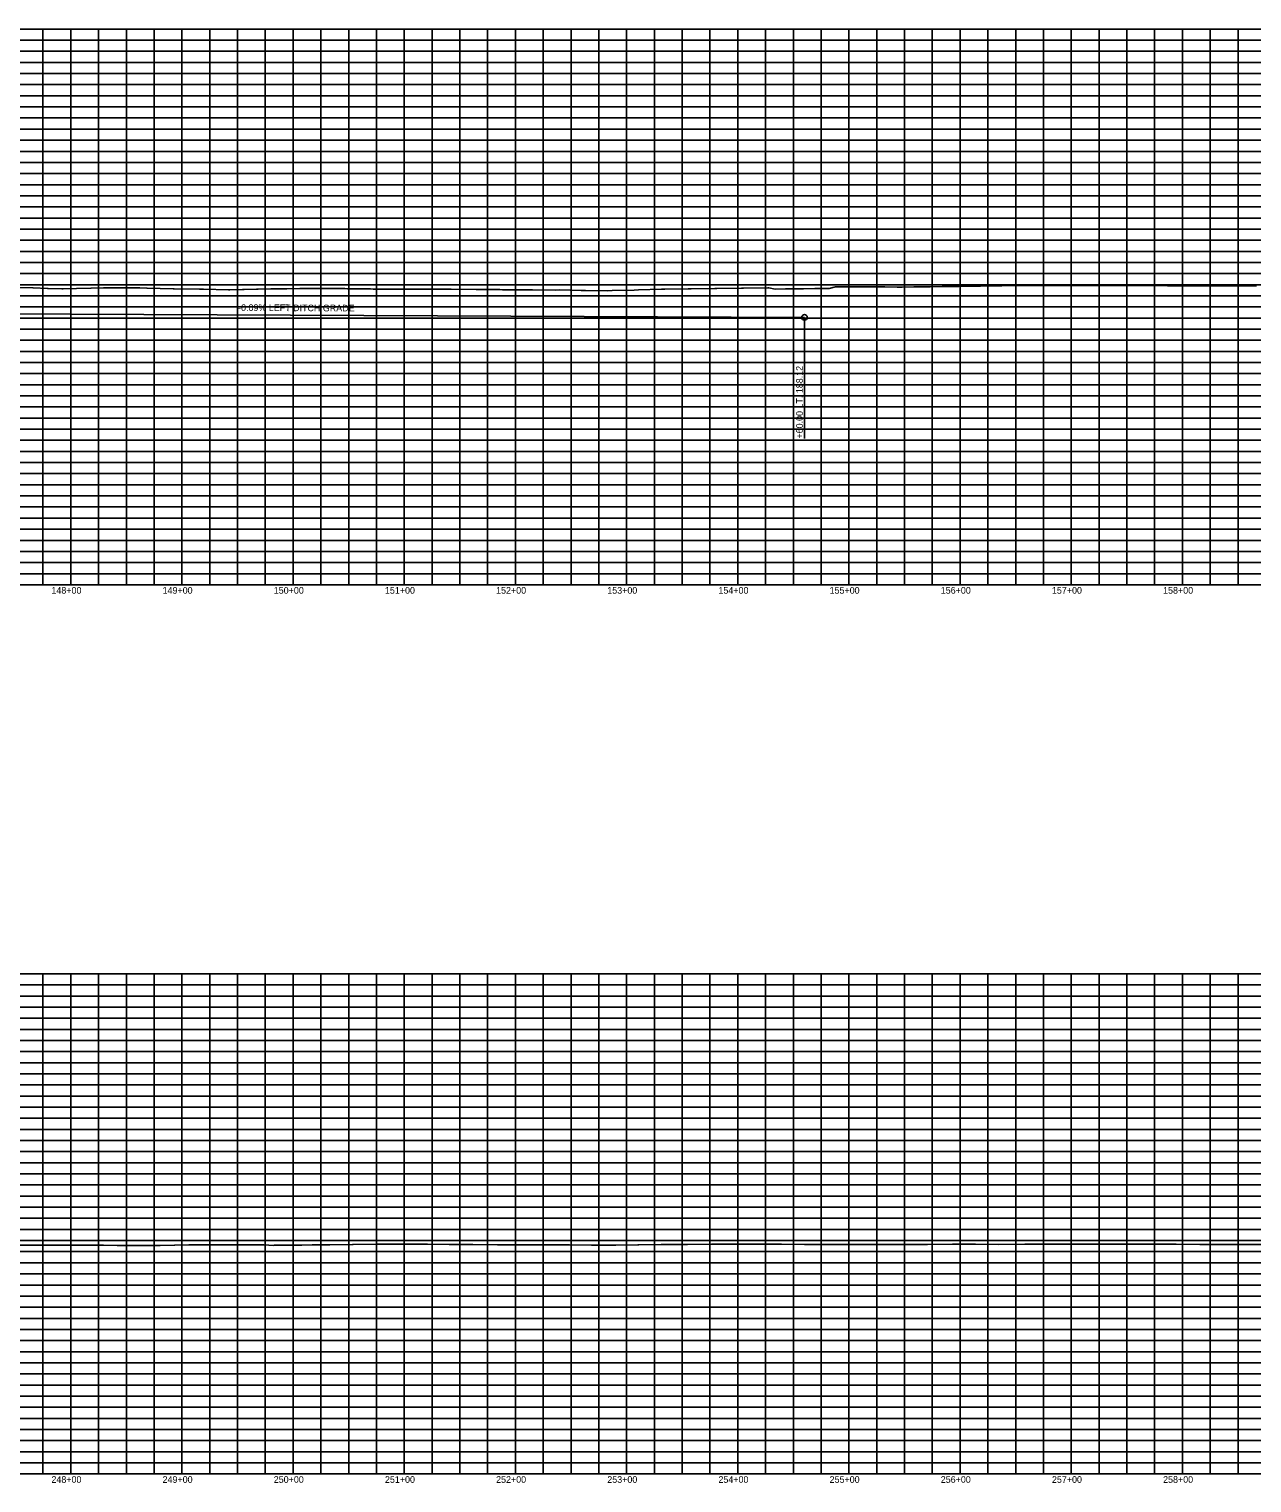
# Model space of a CAD drawing. Extents: x 1399671 to 1408349, y 1930471 to 1933387.
# Drawn here: x 1405087 to 1406187, y 1932071 to 1933379 of the extents above; entities that cross this region are included whole.
import ezdxf

# ---------------------------------------------------------------- set-up
doc = ezdxf.new("R2010")
doc.units = 0
for name, color, linetype in [('R_Exist Surface', 7, 'Continuous'), ('R_Grid', 7, 'Continuous'), ('R_Grid Annot', 7, 'Continuous'), ('R_Vert Alg', 7, 'Continuous'), ('R_Vert Alg Annot', 7, 'Continuous')]:
    doc.layers.add(name, color=color, linetype=linetype)

msp = doc.modelspace()

# ---------------------------------------------------------------- linework, layer by layer
at = {"layer": 'R_Exist Surface'}
for points in [[(1405077.4, 1933146), (1405090.1, 1933145.8), (1405090.3, 1933145.8), (1405090.3, 1933145.8), (1405103.3, 1933145.3), (1405103.8, 1933145.3), (1405116.3, 1933144.9), (1405117.2, 1933144.9), (1405129.4, 1933145.2), (1405142.3, 1933145.5), (1405142.5, 1933145.5), (1405153.5, 1933145.7), (1405155.7, 1933145.7), (1405155.8, 1933145.7), (1405168.7, 1933145.8), (1405170.1, 1933145.8), (1405186.2, 1933145.7), (1405192.7, 1933145.5), (1405193, 1933145.5), (1405216.2, 1933145), (1405217.3, 1933145), (1405240, 1933144.7), (1405241.7, 1933144.6), (1405243.6, 1933144.5), (1405266, 1933144.1), (1405267.4, 1933144.1), (1405278.7, 1933144.3), (1405280.1, 1933144.4), (1405291.4, 1933144.6), (1405292.8, 1933144.6), (1405304.1, 1933144.8), (1405305.5, 1933144.8), (1405316.8, 1933145), (1405318.4, 1933145), (1405330.3, 1933145.1), (1405331.8, 1933145.1), (1405343.8, 1933145.1), (1405345.2, 1933145.1), (1405357.3, 1933145.1), (1405369.6, 1933145.1), (1405370.8, 1933145.1), (1405373, 1933145), (1405393.8, 1933144.8), (1405396.1, 1933144.7), (1405416.9, 1933144.6), (1405419.2, 1933144.6), (1405440.9, 1933144.6), (1405442.8, 1933144.6), (1405465, 1933144.7), (1405466.5, 1933144.6), (1405488.8, 1933144.4), (1405510.2, 1933144.2), (1405512.7, 1933144), (1405533.1, 1933143.9), (1405536.4, 1933143.9), (1405539.4, 1933144), (1405560.1, 1933143.8), (1405563.5, 1933143.9), (1405583.4, 1933143.5), (1405587.2, 1933143.5), (1405606.7, 1933143.1), (1405611.1, 1933143.3), (1405631.1, 1933143.8), (1405634.8, 1933143.9), (1405655.5, 1933144.5), (1405658.6, 1933144.6), (1405679.6, 1933144.8), (1405682.2, 1933145), (1405703.7, 1933145.2), (1405705.4, 1933145.2), (1405727.4, 1933145.5), (1405729.2, 1933145.5), (1405751.2, 1933145.8), (1405752, 1933145.9), (1405757.7, 1933144.7), (1405767, 1933144.8), (1405776.3, 1933144.8), (1405780.4, 1933144.9), (1405783.4, 1933145), (1405793.4, 1933145.1), (1405796.3, 1933145.2), (1405806.4, 1933145.2), (1405812.2, 1933146.8), (1405815, 1933146.8), (1405826, 1933146.7), (1405828.8, 1933146.8), (1405839.9, 1933146.7), (1405842.6, 1933146.7), (1405853.7, 1933146.6), (1405856.4, 1933146.6), (1405867.6, 1933146.5), (1405872.2, 1933146.5), (1405882.6, 1933146.7), (1405893.4, 1933146.8), (1405897.4, 1933146.8), (1405908.2, 1933147), (1405919.3, 1933147.1), (1405923, 1933147.1), (1405938.8, 1933147.3), (1405942.4, 1933147.4), (1405958.2, 1933147.6), (1405961.7, 1933147.6), (1405977.6, 1933147.8), (1405993.5, 1933148), (1405996.9, 1933148), (1406014, 1933148), (1406020, 1933147.9), (1406035.3, 1933147.9), (1406043.2, 1933147.8), (1406053.3, 1933147.8), (1406060.5, 1933147.8), (1406070.7, 1933147.8), (1406081.3, 1933147.8), (1406087.9, 1933147.8), (1406098.5, 1933147.8), (1406105.2, 1933147.8), (1406110.7, 1933147.7), (1406123.1, 1933147.7), (1406130.1, 1933147.7), (1406147.6, 1933147.7), (1406155.4, 1933147.7), (1406164.6, 1933147.7), (1406173.5, 1933147.7), (1406182, 1933147.7), (1406190.8, 1933147.7)], [(1405076.8, 1932284.5), (1405089.3, 1932284.5), (1405089.6, 1932284.5), (1405102.2, 1932284.5), (1405102.4, 1932284.5), (1405115, 1932284.4), (1405115.3, 1932284.4), (1405127.8, 1932284.4), (1405128.1, 1932284.4), (1405140.7, 1932284.3), (1405141, 1932284.3), (1405153.3, 1932284.3), (1405153.6, 1932284.3), (1405166, 1932284.2), (1405166.2, 1932284.2), (1405178.6, 1932284.1), (1405178.9, 1932284.1), (1405191.3, 1932284.1), (1405191.5, 1932284.1), (1405204.4, 1932284.2), (1405204.6, 1932284.2), (1405217.4, 1932284.4), (1405217.7, 1932284.4), (1405230.5, 1932284.6), (1405230.7, 1932284.6), (1405230.9, 1932284.6), (1405243.8, 1932284.7), (1405244, 1932284.7), (1405257.2, 1932284.7), (1405257.5, 1932284.7), (1405270.7, 1932284.7), (1405283.7, 1932284.6), (1405284.1, 1932284.6), (1405297.1, 1932284.6), (1405297.5, 1932284.6), (1405297.8, 1932284.6), (1405306.8, 1932284.2), (1405307.3, 1932284.3), (1405331, 1932284.5), (1405331.5, 1932284.5), (1405332, 1932284.5), (1405341.4, 1932284.6), (1405355.6, 1932284.7), (1405356.2, 1932284.7), (1405357.1, 1932284.7), (1405377.5, 1932284.9), (1405378.3, 1932285), (1405398.8, 1932285.2), (1405399.6, 1932285.2), (1405421.5, 1932285.2), (1405422.3, 1932285.2), (1405444.1, 1932285.2), (1405445, 1932285.2), (1405464.6, 1932285.1), (1405465.4, 1932285.1), (1405485, 1932284.9), (1405486, 1932284.9), (1405508.2, 1932284.8), (1405509.3, 1932284.8), (1405531.4, 1932284.6), (1405532.4, 1932284.6), (1405552.1, 1932284.6), (1405553.1, 1932284.6), (1405572.8, 1932284.6), (1405592.7, 1932284.5), (1405593.7, 1932284.5), (1405613.6, 1932284.4), (1405614.6, 1932284.4), (1405634.4, 1932284.6), (1405635.3, 1932284.6), (1405655.3, 1932284.9), (1405656, 1932284.9), (1405656.7, 1932284.9), (1405678.3, 1932285.1), (1405678.9, 1932285.1), (1405700.5, 1932285.3), (1405701.1, 1932285.3), (1405721.4, 1932285.2), (1405722, 1932285.2), (1405742.2, 1932285.2), (1405743, 1932285.2), (1405763.2, 1932285.2), (1405763.6, 1932285.2), (1405784.2, 1932285.1), (1405784.3, 1932285.1), (1405806.6, 1932285.1), (1405828.5, 1932285), (1405829, 1932285), (1405849.6, 1932285), (1405850, 1932285), (1405850.5, 1932285), (1405871.1, 1932285), (1405871.7, 1932285), (1405894.3, 1932285.1), (1405894.8, 1932285.1), (1405917.4, 1932285.2), (1405918, 1932285.2), (1405937.9, 1932285.2), (1405958.3, 1932285.1), (1405958.4, 1932285.1), (1405982.4, 1932285.2), (1405982.5, 1932285.2), (1406000.2, 1932285.2), (1406006.5, 1932285.2), (1406006.5, 1932285.2), (1406029, 1932285.3), (1406029.2, 1932285.3), (1406051.5, 1932285.4), (1406051.9, 1932285.4), (1406052.3, 1932285.4), (1406072.9, 1932285.4), (1406073.3, 1932285.4), (1406094, 1932285.4), (1406094.4, 1932285.4), (1406096.5, 1932285.4), (1406116.9, 1932285.2), (1406117.3, 1932285.2), (1406118.4, 1932285.2), (1406139.8, 1932285.1), (1406140.2, 1932285.1), (1406145.5, 1932285.1), (1406161.4, 1932285), (1406161.6, 1932285), (1406161.8, 1932285), (1406162.1, 1932285), (1406183.4, 1932285), (1406184, 1932285), (1406204.8, 1932285)]]:
    msp.add_lwpolyline(points, dxfattribs=at)
at = {"layer": 'R_Grid'}
for p, q in [((1400324.2, 1933378.6), (1408224.2, 1933378.6)), ((1400324.2, 1933378.6), (1408224.2, 1933378.6)), ((1405099.2, 1932878.6), (1405099.2, 1933378.6)), ((1405124.2, 1932878.6), (1405124.2, 1933378.6)), ((1405149.2, 1932878.6), (1405149.2, 1933378.6)), ((1405174.2, 1932878.6), (1405174.2, 1933378.6)), ((1405199.2, 1932878.6), (1405199.2, 1933378.6)), ((1405224.2, 1932878.6), (1405224.2, 1933378.6)), ((1405249.2, 1932878.6), (1405249.2, 1933378.6)), ((1405274.2, 1932878.6), (1405274.2, 1933378.6)), ((1405299.2, 1932878.6), (1405299.2, 1933378.6)), ((1405324.2, 1932878.6), (1405324.2, 1933378.6)), ((1405349.2, 1932878.6), (1405349.2, 1933378.6)), ((1405374.2, 1932878.6), (1405374.2, 1933378.6)), ((1405399.2, 1932878.6), (1405399.2, 1933378.6)), ((1405424.2, 1932878.6), (1405424.2, 1933378.6)), ((1405449.2, 1932878.6), (1405449.2, 1933378.6)), ((1405474.2, 1932878.6), (1405474.2, 1933378.6)), ((1405499.2, 1932878.6), (1405499.2, 1933378.6)), ((1405524.2, 1932878.6), (1405524.2, 1933378.6)), ((1405549.2, 1932878.6), (1405549.2, 1933378.6)), ((1405574.2, 1932878.6), (1405574.2, 1933378.6)), ((1405599.2, 1932878.6), (1405599.2, 1933378.6)), ((1405624.2, 1932878.6), (1405624.2, 1933378.6)), ((1405649.2, 1932878.6), (1405649.2, 1933378.6)), ((1405674.2, 1932878.6), (1405674.2, 1933378.6)), ((1405699.2, 1932878.6), (1405699.2, 1933378.6)), ((1405724.2, 1932878.6), (1405724.2, 1933378.6)), ((1405749.2, 1932878.6), (1405749.2, 1933378.6)), ((1405774.2, 1932878.6), (1405774.2, 1933378.6)), ((1405799.2, 1932878.6), (1405799.2, 1933378.6)), ((1405824.2, 1932878.6), (1405824.2, 1933378.6)), ((1405849.2, 1932878.6), (1405849.2, 1933378.6)), ((1405874.2, 1932878.6), (1405874.2, 1933378.6)), ((1405899.2, 1932878.6), (1405899.2, 1933378.6)), ((1405924.2, 1932878.6), (1405924.2, 1933378.6)), ((1405949.2, 1932878.6), (1405949.2, 1933378.6)), ((1405974.2, 1932878.6), (1405974.2, 1933378.6)), ((1405999.2, 1932878.6), (1405999.2, 1933378.6)), ((1406024.2, 1932878.6), (1406024.2, 1933378.6)), ((1406049.2, 1932878.6), (1406049.2, 1933378.6)), ((1406074.2, 1932878.6), (1406074.2, 1933378.6)), ((1406099.2, 1932878.6), (1406099.2, 1933378.6)), ((1406124.2, 1932878.6), (1406124.2, 1933378.6)), ((1406149.2, 1932878.6), (1406149.2, 1933378.6)), ((1406174.2, 1932878.6), (1406174.2, 1933378.6)), ((1400324.2, 1933368.6), (1408224.2, 1933368.6)), ((1400324.2, 1933358.6), (1408224.2, 1933358.6)), ((1400324.2, 1933348.6), (1408224.2, 1933348.6)), ((1400324.2, 1933338.6), (1408224.2, 1933338.6)), ((1400324.2, 1933328.6), (1408224.2, 1933328.6)), ((1400324.2, 1933318.6), (1408224.2, 1933318.6)), ((1400324.2, 1933308.6), (1408224.2, 1933308.6)), ((1400324.2, 1933298.6), (1408224.2, 1933298.6)), ((1400324.2, 1933288.6), (1408224.2, 1933288.6)), ((1400324.2, 1933278.6), (1408224.2, 1933278.6)), ((1400324.2, 1933268.6), (1408224.2, 1933268.6)), ((1400324.2, 1933258.6), (1408224.2, 1933258.6)), ((1400324.2, 1933248.6), (1408224.2, 1933248.6)), ((1400324.2, 1933238.6), (1408224.2, 1933238.6)), ((1400324.2, 1933228.6), (1408224.2, 1933228.6)), ((1400324.2, 1933218.6), (1408224.2, 1933218.6)), ((1400324.2, 1933208.6), (1408224.2, 1933208.6)), ((1400324.2, 1933198.6), (1408224.2, 1933198.6)), ((1400324.2, 1933188.6), (1408224.2, 1933188.6)), ((1400324.2, 1933178.6), (1408224.2, 1933178.6)), ((1400324.2, 1933168.6), (1408224.2, 1933168.6)), ((1400324.2, 1933158.6), (1408224.2, 1933158.6)), ((1400324.2, 1933148.6), (1408224.2, 1933148.6)), ((1400324.2, 1933138.6), (1408224.2, 1933138.6)), ((1400324.2, 1933128.6), (1408224.2, 1933128.6)), ((1400324.2, 1933118.6), (1408224.2, 1933118.6)), ((1400324.2, 1933108.6), (1408224.2, 1933108.6)), ((1400324.2, 1933098.6), (1408224.2, 1933098.6)), ((1400324.2, 1933088.6), (1408224.2, 1933088.6)), ((1400324.2, 1933078.6), (1408224.2, 1933078.6)), ((1400324.2, 1933068.6), (1408224.2, 1933068.6)), ((1400324.2, 1933058.6), (1408224.2, 1933058.6)), ((1400324.2, 1933048.6), (1408224.2, 1933048.6)), ((1400324.2, 1933038.6), (1408224.2, 1933038.6)), ((1400324.2, 1933028.6), (1408224.2, 1933028.6)), ((1400324.2, 1933018.6), (1408224.2, 1933018.6)), ((1400324.2, 1933008.6), (1408224.2, 1933008.6)), ((1400324.2, 1932998.6), (1408224.2, 1932998.6)), ((1400324.2, 1932988.6), (1408224.2, 1932988.6)), ((1400324.2, 1932978.6), (1408224.2, 1932978.6)), ((1400324.2, 1932968.6), (1408224.2, 1932968.6)), ((1400324.2, 1932958.6), (1408224.2, 1932958.6)), ((1400324.2, 1932948.6), (1408224.2, 1932948.6)), ((1400324.2, 1932938.6), (1408224.2, 1932938.6)), ((1400324.2, 1932928.6), (1408224.2, 1932928.6)), ((1400324.2, 1932918.6), (1408224.2, 1932918.6)), ((1400324.2, 1932908.6), (1408224.2, 1932908.6)), ((1400324.2, 1932898.6), (1408224.2, 1932898.6)), ((1400324.2, 1932888.6), (1408224.2, 1932888.6)), ((1400324.2, 1932878.6), (1408224.2, 1932878.6)), ((1400324.2, 1932528.6), (1407124.2, 1932528.6)), ((1400324.2, 1932528.6), (1407124.2, 1932528.6)), ((1405099.2, 1932078.6), (1405099.2, 1932528.6)), ((1405124.2, 1932078.6), (1405124.2, 1932528.6)), ((1405149.2, 1932078.6), (1405149.2, 1932528.6)), ((1405174.2, 1932078.6), (1405174.2, 1932528.6)), ((1405199.2, 1932078.6), (1405199.2, 1932528.6)), ((1405224.2, 1932078.6), (1405224.2, 1932528.6)), ((1405249.2, 1932078.6), (1405249.2, 1932528.6)), ((1405274.2, 1932078.6), (1405274.2, 1932528.6)), ((1405299.2, 1932078.6), (1405299.2, 1932528.6)), ((1405324.2, 1932078.6), (1405324.2, 1932528.6)), ((1405349.2, 1932078.6), (1405349.2, 1932528.6)), ((1405374.2, 1932078.6), (1405374.2, 1932528.6)), ((1405399.2, 1932078.6), (1405399.2, 1932528.6)), ((1405424.2, 1932078.6), (1405424.2, 1932528.6)), ((1405449.2, 1932078.6), (1405449.2, 1932528.6)), ((1405474.2, 1932078.6), (1405474.2, 1932528.6)), ((1405499.2, 1932078.6), (1405499.2, 1932528.6)), ((1405524.2, 1932078.6), (1405524.2, 1932528.6)), ((1405549.2, 1932078.6), (1405549.2, 1932528.6)), ((1405574.2, 1932078.6), (1405574.2, 1932528.6)), ((1405599.2, 1932078.6), (1405599.2, 1932528.6)), ((1405624.2, 1932078.6), (1405624.2, 1932528.6)), ((1405649.2, 1932078.6), (1405649.2, 1932528.6)), ((1405674.2, 1932078.6), (1405674.2, 1932528.6)), ((1405699.2, 1932078.6), (1405699.2, 1932528.6)), ((1405724.2, 1932078.6), (1405724.2, 1932528.6)), ((1405749.2, 1932078.6), (1405749.2, 1932528.6)), ((1405774.2, 1932078.6), (1405774.2, 1932528.6)), ((1405799.2, 1932078.6), (1405799.2, 1932528.6)), ((1405824.2, 1932078.6), (1405824.2, 1932528.6)), ((1405849.2, 1932078.6), (1405849.2, 1932528.6)), ((1405874.2, 1932078.6), (1405874.2, 1932528.6)), ((1405899.2, 1932078.6), (1405899.2, 1932528.6)), ((1405924.2, 1932078.6), (1405924.2, 1932528.6)), ((1405949.2, 1932078.6), (1405949.2, 1932528.6)), ((1405974.2, 1932078.6), (1405974.2, 1932528.6)), ((1405999.2, 1932078.6), (1405999.2, 1932528.6)), ((1406024.2, 1932078.6), (1406024.2, 1932528.6)), ((1406049.2, 1932078.6), (1406049.2, 1932528.6)), ((1406074.2, 1932078.6), (1406074.2, 1932528.6)), ((1406099.2, 1932078.6), (1406099.2, 1932528.6)), ((1406124.2, 1932078.6), (1406124.2, 1932528.6)), ((1406149.2, 1932078.6), (1406149.2, 1932528.6)), ((1406174.2, 1932078.6), (1406174.2, 1932528.6)), ((1400324.2, 1932518.6), (1407124.2, 1932518.6)), ((1400324.2, 1932508.6), (1407124.2, 1932508.6)), ((1400324.2, 1932498.6), (1407124.2, 1932498.6)), ((1400324.2, 1932488.6), (1407124.2, 1932488.6)), ((1400324.2, 1932478.6), (1407124.2, 1932478.6)), ((1400324.2, 1932468.6), (1407124.2, 1932468.6)), ((1400324.2, 1932458.6), (1407124.2, 1932458.6)), ((1400324.2, 1932448.6), (1407124.2, 1932448.6)), ((1400324.2, 1932438.6), (1407124.2, 1932438.6)), ((1400324.2, 1932428.6), (1407124.2, 1932428.6)), ((1400324.2, 1932418.6), (1407124.2, 1932418.6)), ((1400324.2, 1932408.6), (1407124.2, 1932408.6)), ((1400324.2, 1932398.6), (1407124.2, 1932398.6)), ((1400324.2, 1932388.6), (1407124.2, 1932388.6)), ((1400324.2, 1932378.6), (1407124.2, 1932378.6)), ((1400324.2, 1932368.6), (1407124.2, 1932368.6)), ((1400324.2, 1932358.6), (1407124.2, 1932358.6)), ((1400324.2, 1932348.6), (1407124.2, 1932348.6)), ((1400324.2, 1932338.6), (1407124.2, 1932338.6)), ((1400324.2, 1932328.6), (1407124.2, 1932328.6)), ((1400324.2, 1932318.6), (1407124.2, 1932318.6)), ((1400324.2, 1932308.6), (1407124.2, 1932308.6)), ((1400324.2, 1932298.6), (1407124.2, 1932298.6)), ((1400324.2, 1932288.6), (1407124.2, 1932288.6)), ((1400324.2, 1932278.6), (1407124.2, 1932278.6)), ((1400324.2, 1932268.6), (1407124.2, 1932268.6)), ((1400324.2, 1932258.6), (1407124.2, 1932258.6)), ((1400324.2, 1932248.6), (1407124.2, 1932248.6)), ((1400324.2, 1932238.6), (1407124.2, 1932238.6)), ((1400324.2, 1932228.6), (1407124.2, 1932228.6)), ((1400324.2, 1932218.6), (1407124.2, 1932218.6)), ((1400324.2, 1932208.6), (1407124.2, 1932208.6)), ((1400324.2, 1932198.6), (1407124.2, 1932198.6)), ((1400324.2, 1932188.6), (1407124.2, 1932188.6)), ((1400324.2, 1932178.6), (1407124.2, 1932178.6)), ((1400324.2, 1932168.6), (1407124.2, 1932168.6)), ((1400324.2, 1932158.6), (1407124.2, 1932158.6)), ((1400324.2, 1932148.6), (1407124.2, 1932148.6)), ((1400324.2, 1932138.6), (1407124.2, 1932138.6)), ((1400324.2, 1932128.6), (1407124.2, 1932128.6)), ((1400324.2, 1932118.6), (1407124.2, 1932118.6)), ((1400324.2, 1932108.6), (1407124.2, 1932108.6)), ((1400324.2, 1932098.6), (1407124.2, 1932098.6)), ((1400324.2, 1932088.6), (1407124.2, 1932088.6)), ((1400324.2, 1932078.6), (1407124.2, 1932078.6))]:
    msp.add_line(p, q, dxfattribs=at)
at = {"layer": 'R_Vert Alg'}
msp.add_line((1404902.2, 1933123.2), (1405784.2, 1933119.2), dxfattribs=at)
at = {"layer": 'R_Vert Alg Annot'}
for p, q in [((1405784.2, 1933119.2), (1405784.2, 1933094.2)), ((1405784.2, 1933094.2), (1405784.2, 1933010.2))]:
    msp.add_line(p, q, dxfattribs=at)
msp.add_circle((1405784.2, 1933119.2), 2.5, dxfattribs=at)

# ---------------------------------------------------------------- texts
at = {"layer": 'R_Grid Annot'}
for s, p in [('148+00', (1405106.8, 1932870.6)), ('149+00', (1405206.8, 1932870.6)), ('150+00', (1405306.8, 1932870.6)), ('151+00', (1405406.8, 1932870.6)), ('152+00', (1405506.8, 1932870.6)), ('153+00', (1405606.8, 1932870.6)), ('154+00', (1405706.8, 1932870.6)), ('155+00', (1405806.8, 1932870.6)), ('156+00', (1405906.8, 1932870.6)), ('157+00', (1406006.8, 1932870.6)), ('158+00', (1406106.8, 1932870.6)), ('248+00', (1405106.8, 1932070.6)), ('249+00', (1405206.8, 1932070.6)), ('250+00', (1405306.8, 1932070.6)), ('251+00', (1405406.8, 1932070.6)), ('252+00', (1405506.8, 1932070.6)), ('253+00', (1405606.8, 1932070.6)), ('254+00', (1405706.8, 1932070.6)), ('255+00', (1405806.8, 1932070.6)), ('256+00', (1405906.8, 1932070.6)), ('257+00', (1406006.8, 1932070.6)), ('258+00', (1406106.8, 1932070.6))]:
    msp.add_text(s, height=6, dxfattribs=at).set_placement(p)
at = {"layer": 'R_Vert Alg Annot'}
for s, rotation, p in [('-0.09% LEFT DITCH GRADE', 359.7434, (1405274.7, 1933125)), ('+60.00 LT. 188.12', 90, (1405782.7, 1933010.2))]:
    msp.add_text(s, height=6, rotation=rotation, dxfattribs=at).set_placement(p)

doc.saveas('drawing.dxf')
